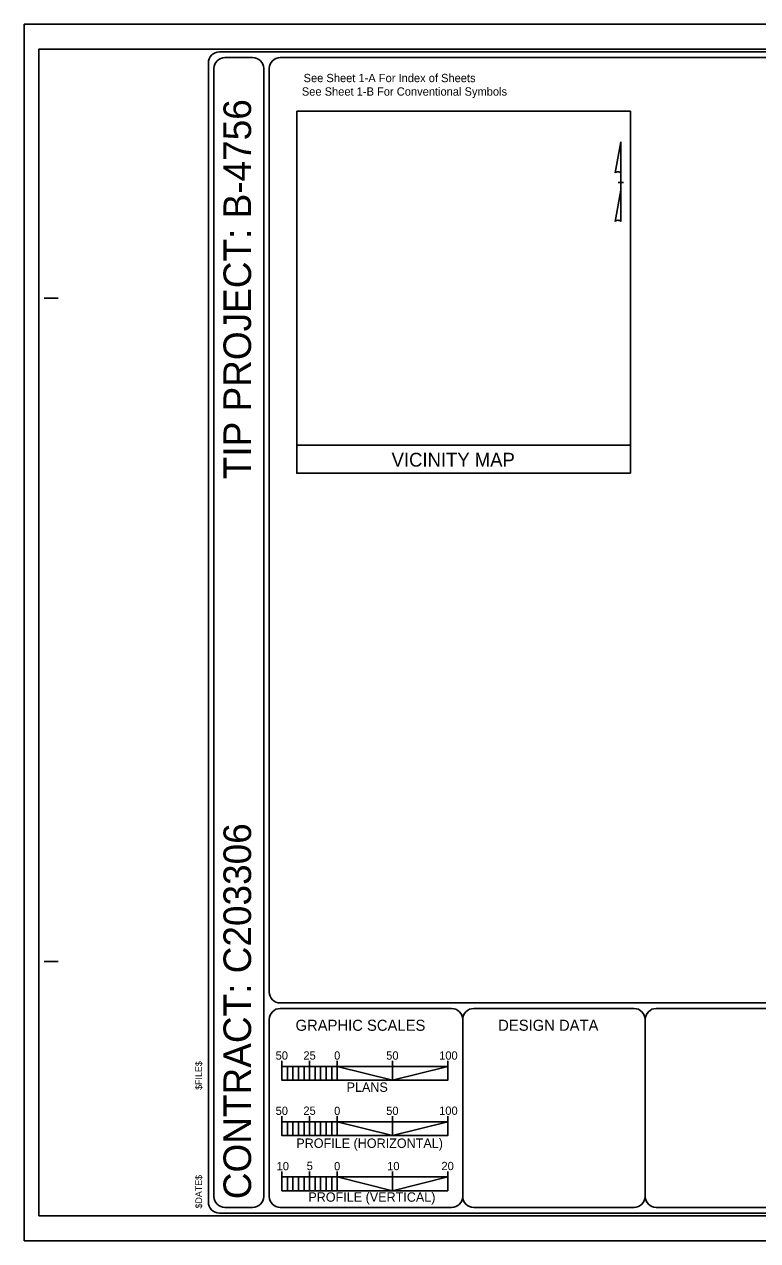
# Model space of a CAD drawing. Extents: x 2431000 to 2534000, y 645879 to 714000.
# Drawn here: x 2463853 to 2464516, y 678900 to 680000 of the extents above; entities that cross this region are included whole.
import ezdxf

# ---------------------------------------------------------------- set-up
doc = ezdxf.new("R2010")
doc.units = 0
for name, color, linetype in [('Prop Dimension', 7, 'Continuous'), ('Prop Dimension Text', 7, 'Continuous'), ('Prop Terminator CELL', 7, 'Continuous'), ('Sheet Summary CELL', 7, 'Continuous'), ('Sheet Typical CELL', 7, 'Continuous')]:
    doc.layers.add(name, color=color, linetype=linetype)

msp = doc.modelspace()

# ---------------------------------------------------------------- linework, layer by layer
at = {"layer": 'Prop Dimension'}
msp.add_lwpolyline([(2463853.2, 678900), (2465536.7, 678900), (2465536.7, 680000), (2463853.2, 680000)], close=True, dxfattribs=at)
at = {"layer": 'Prop Dimension Text'}
for p, q in [((2464069.7, 678940), (2464069.7, 679960)), ((2464074.7, 679125), (2464074.7, 679960)), ((2463871.2, 679752.5), (2463883.7, 679752.5)), ((2463871.2, 679752.5), (2463883.7, 679752.5)), ((2463871.2, 679152.5), (2463883.7, 679152.5)), ((2463871.2, 679152.5), (2463883.7, 679152.5)), ((2464084.7, 679115), (2465504.7, 679115)), ((2464084.7, 679110), (2464239.7, 679110)), ((2464259.7, 679110), (2464404.7, 679110)), ((2464424.7, 679110), (2464804.7, 679110)), ((2464074.7, 678940), (2464074.7, 679100)), ((2464249.7, 679100), (2464249.7, 678940)), ((2464414.7, 679100), (2464414.7, 678940)), ((2464086.2, 679057.6), (2464086.2, 679062.6)), ((2464086.2, 679062.6), (2464086.2, 679062.6)), ((2464086.2, 679057.6), (2464086.2, 679045.1)), ((2464086.2, 679057.6), (2464086.2, 679057.6)), ((2464236.2, 679057.6), (2464086.2, 679057.6)), ((2464111.2, 679057.6), (2464111.2, 679062.6)), ((2464121.2, 679057.6), (2464121.2, 679045.1)), ((2464136.2, 679057.6), (2464136.2, 679062.6)), ((2464186.2, 679057.6), (2464186.2, 679062.6)), ((2464186.2, 679057.6), (2464186.2, 679045.1)), ((2464236.2, 679057.6), (2464236.2, 679062.6)), ((2464236.2, 679045.1), (2464236.2, 679057.6)), ((2464086.2, 679045.1), (2464236.2, 679045.1)), ((2464086.2, 679007.6), (2464086.2, 679012.6)), ((2464086.2, 679007.6), (2464086.2, 679012.6)), ((2464086.2, 679012.6), (2464086.2, 679012.6)), ((2464111.2, 679007.6), (2464111.2, 679012.6)), ((2464111.2, 679007.6), (2464111.2, 679012.6)), ((2464136.2, 679007.6), (2464136.2, 679012.6)), ((2464136.2, 679007.6), (2464136.2, 679012.6)), ((2464186.2, 679007.6), (2464186.2, 679012.6)), ((2464186.2, 679007.6), (2464186.2, 679012.6)), ((2464236.2, 679007.6), (2464236.2, 679012.6)), ((2464236.2, 679007.6), (2464236.2, 679012.6)), ((2464086.2, 679007.6), (2464086.2, 678995.1)), ((2464086.2, 679007.6), (2464086.2, 679007.6)), ((2464236.2, 679007.6), (2464086.2, 679007.6)), ((2464086.2, 679007.6), (2464086.2, 679007.6)), ((2464236.2, 679007.6), (2464086.2, 679007.6)), ((2464121.2, 679007.6), (2464121.2, 678995.1)), ((2464186.2, 679007.6), (2464186.2, 678995.1)), ((2464236.2, 678995.1), (2464236.2, 679007.6)), ((2464086.2, 678995.1), (2464236.2, 678995.1)), ((2464086.2, 678957.6), (2464086.2, 678962.6)), ((2464086.2, 678957.6), (2464086.2, 678962.6)), ((2464086.2, 678957.6), (2464086.2, 678962.6)), ((2464086.2, 678962.6), (2464086.2, 678962.6)), ((2464086.2, 678957.6), (2464086.2, 678945.1)), ((2464086.2, 678957.6), (2464086.2, 678957.6)), ((2464236.2, 678957.6), (2464086.2, 678957.6)), ((2464086.2, 678957.6), (2464086.2, 678957.6)), ((2464236.2, 678957.6), (2464086.2, 678957.6)), ((2464086.2, 678957.6), (2464086.2, 678957.6)), ((2464236.2, 678957.6), (2464086.2, 678957.6)), ((2464111.2, 678957.6), (2464111.2, 678962.6)), ((2464111.2, 678957.6), (2464111.2, 678962.6)), ((2464111.2, 678957.6), (2464111.2, 678962.6)), ((2464121.2, 678957.6), (2464121.2, 678945.1)), ((2464136.2, 678957.6), (2464136.2, 678962.6)), ((2464136.2, 678957.6), (2464136.2, 678962.6)), ((2464136.2, 678957.6), (2464136.2, 678962.6)), ((2464186.2, 678957.6), (2464186.2, 678962.6)), ((2464186.2, 678957.6), (2464186.2, 678962.6)), ((2464186.2, 678957.6), (2464186.2, 678962.6)), ((2464186.2, 678957.6), (2464186.2, 678945.1)), ((2464236.2, 678957.6), (2464236.2, 678962.6)), ((2464236.2, 678957.6), (2464236.2, 678962.6)), ((2464236.2, 678957.6), (2464236.2, 678962.6)), ((2464236.2, 678945.1), (2464236.2, 678957.6)), ((2464086.2, 678945.1), (2464236.2, 678945.1)), ((2464019.7, 678925), (2464019.7, 678925)), ((2464019.7, 678925), (2464019.7, 678925)), ((2464019.7, 678925), (2464019.7, 678925)), ((2464019.7, 678925), (2464019.7, 678925))]:
    msp.add_line(p, q, dxfattribs=at)
for points in [[(2465509.7, 679975), (2464029.7, 679975)], [(2464059.7, 679970), (2464034.7, 679970)], [(2465504.7, 679970), (2464084.7, 679970)], [(2464019.7, 679965), (2464019.7, 678935)], [(2464019.7, 679965), (2464019.7, 678935)], [(2464024.7, 679960), (2464024.7, 678940)], [(2464029.7, 678925), (2465509.7, 678925)], [(2464034.7, 678930), (2464059.7, 678930)], [(2464084.7, 678930), (2464239.7, 678930)], [(2464259.7, 678930), (2464404.7, 678930)], [(2464424.7, 678930), (2464804.7, 678930)]]:
    msp.add_lwpolyline(points, dxfattribs=at)
for points in [[(2464086.2, 679057.6), (2464091.2, 679057.6), (2464091.2, 679045.1), (2464086.2, 679045.1)], [(2464096.2, 679057.6), (2464101.2, 679057.6), (2464101.2, 679045.1), (2464096.2, 679045.1)], [(2464106.2, 679057.6), (2464111.2, 679057.6), (2464111.2, 679045.1), (2464106.2, 679045.1)], [(2464116.2, 679057.6), (2464121.2, 679057.6), (2464121.2, 679045.1), (2464116.2, 679045.1)], [(2464126.2, 679057.6), (2464131.2, 679057.6), (2464131.2, 679045.1), (2464126.2, 679045.1)], [(2464136.2, 679057.6), (2464186.2, 679045.1), (2464136.2, 679045.1)], [(2464236.2, 679057.6), (2464186.2, 679045.1), (2464236.2, 679045.1)], [(2464086.2, 679007.6), (2464091.2, 679007.6), (2464091.2, 678995.1), (2464086.2, 678995.1)], [(2464096.2, 679007.6), (2464101.2, 679007.6), (2464101.2, 678995.1), (2464096.2, 678995.1)], [(2464106.2, 679007.6), (2464111.2, 679007.6), (2464111.2, 678995.1), (2464106.2, 678995.1)], [(2464116.2, 679007.6), (2464121.2, 679007.6), (2464121.2, 678995.1), (2464116.2, 678995.1)], [(2464126.2, 679007.6), (2464131.2, 679007.6), (2464131.2, 678995.1), (2464126.2, 678995.1)], [(2464136.2, 679007.6), (2464186.2, 678995.1), (2464136.2, 678995.1)], [(2464236.2, 679007.6), (2464186.2, 678995.1), (2464236.2, 678995.1)], [(2464086.2, 678957.6), (2464091.2, 678957.6), (2464091.2, 678945.1), (2464086.2, 678945.1)], [(2464096.2, 678957.6), (2464101.2, 678957.6), (2464101.2, 678945.1), (2464096.2, 678945.1)], [(2464106.2, 678957.6), (2464111.2, 678957.6), (2464111.2, 678945.1), (2464106.2, 678945.1)], [(2464116.2, 678957.6), (2464121.2, 678957.6), (2464121.2, 678945.1), (2464116.2, 678945.1)], [(2464126.2, 678957.6), (2464131.2, 678957.6), (2464131.2, 678945.1), (2464126.2, 678945.1)], [(2464136.2, 678957.6), (2464186.2, 678945.1), (2464136.2, 678945.1)], [(2464236.2, 678957.6), (2464186.2, 678945.1), (2464236.2, 678945.1)]]:
    msp.add_lwpolyline(points, close=True, dxfattribs=at)
for centre, start, end in [((2464029.7, 679965), 90, 180), ((2464034.7, 679960), 90, 180), ((2464059.7, 679960), 0, 90), ((2464084.7, 679960), 90, 180), ((2464084.7, 679125), 180, 270), ((2464084.7, 679100), 90, 180), ((2464239.7, 679100), 0, 90), ((2464259.7, 679100), 90, 180), ((2464404.7, 679100), 0, 90), ((2464424.7, 679100), 90, 180), ((2464029.7, 678935), 180, 270), ((2464034.7, 678940), 180, 270), ((2464059.7, 678940), 270, 0), ((2464084.7, 678940), 180, 270), ((2464239.7, 678940), 270, 0), ((2464259.7, 678940), 180, 270), ((2464404.7, 678940), 270, 0), ((2464424.7, 678940), 180, 270)]:
    msp.add_arc(centre, 10, start, end, dxfattribs=at)
at = {"layer": 'Prop Terminator CELL'}
msp.add_lwpolyline([(2463866.2, 678922.5), (2465532.2, 678922.5), (2465532.2, 679977.5), (2463866.2, 679977.5)], close=True, dxfattribs=at)
at = {"layer": 'Sheet Summary CELL'}
for p, q in [((2464387.6, 679865.8), (2464392.6, 679893.6)), ((2464392.6, 679893.6), (2464392.6, 679893.6)), ((2464392.6, 679893.6), (2464392.6, 679893.6)), ((2464392.6, 679893.6), (2464392.6, 679864.9)), ((2464390.2, 679857), (2464395, 679857)), ((2464392.3, 679857), (2464390.2, 679857)), ((2464390.2, 679857), (2464390.2, 679857)), ((2464392.6, 679850.1), (2464392.6, 679865.8)), ((2464392.6, 679864.9), (2464392.6, 679865.8)), ((2464392.6, 679850.1), (2464387.6, 679821.7)), ((2464392.6, 679821.8), (2464392.6, 679850.1))]:
    msp.add_line(p, q, dxfattribs=at)
for centre, start_param, end_param in [((2464390.1, 679865.5), 0.216388, 2.908219), ((2464390.1, 679821.6), 0.201328, 3.141593)]:
    msp.add_ellipse(centre, major_axis=(2.54, -0.02), ratio=0.461098, start_param=start_param, end_param=end_param, dxfattribs=at)
at = {"layer": 'Sheet Typical CELL'}
for p, q in [((2464401.6, 679921.4), (2464099.6, 679921.4)), ((2464099.6, 679921.4), (2464099.6, 679619.4)), ((2464401.6, 679619.4), (2464401.6, 679921.4)), ((2464099.6, 679619.4), (2464401.6, 679619.4))]:
    msp.add_line(p, q, dxfattribs=at)
msp.add_lwpolyline([(2464401.6, 679594), (2464099.6, 679594), (2464099.6, 679619.4), (2464401.6, 679619.4)], close=True, dxfattribs=at)

# ---------------------------------------------------------------- texts
at = {"layer": 'Prop Dimension Text'}
for s, height, p in [('See Sheet 1-A For Index of Sheets', 7.5, (2464105.8, 679947.7)), ('See Sheet 1-B For Conventional Symbols', 7.5, (2464104.2, 679935.5)), ('GRAPHIC SCALES', 10, (2464098.5, 679089.8)), ('DESIGN DATA', 10, (2464281.8, 679089.8)), ('50', 7.5, (2464080.5, 679063.7)), ('25', 7.5, (2464105.6, 679063.7)), ('0', 7.5, (2464133.4, 679063.7)), ('50', 7.5, (2464180.5, 679063.7)), ('100', 7.5, (2464228.4, 679063.7)), ('PLANS', 8.5, (2464144.7, 679034.6)), ('50', 7.5, (2464080.5, 679013.7)), ('25', 7.5, (2464105.6, 679013.8)), ('0', 7.5, (2464133.4, 679013.7)), ('0', 7.5, (2464133.4, 679013.6)), ('50', 7.5, (2464180.5, 679013.7)), ('100', 7.5, (2464228.4, 679013.8)), ('PROFILE (HORIZONTAL)', 8.5, (2464099.2, 678983.9)), ('10', 7.5, (2464081.4, 678963.7)), ('5', 7.5, (2464108.6, 678963.8)), ('0', 7.5, (2464133.4, 678963.7)), ('0', 7.5, (2464133.4, 678963.6)), ('0', 7.5, (2464133.4, 678963.6)), ('10', 7.5, (2464181.4, 678963.7)), ('20', 7.5, (2464230.5, 678963.8)), ('PROFILE (VERTICAL)', 8.5, (2464110.1, 678935.2))]:
    msp.add_text(s, height=height, dxfattribs=at).set_placement(p)
for s, height, p in [('TIP PROJECT: B-4756', 25, (2464058.3, 679588.6)), ('CONTRACT: C203306', 25, (2464058.3, 678937.5)), ('$FILE$', 6, (2464013.9, 679036.4)), ('$DATE$', 6, (2464013.9, 678929.1))]:
    msp.add_text(s, height=height, rotation=90, dxfattribs=at).set_placement(p)
at = {"layer": 'Sheet Typical CELL'}
msp.add_text('VICINITY MAP', height=12.5, dxfattribs=at).set_placement((2464185.4, 679600))

doc.saveas('drawing.dxf')
